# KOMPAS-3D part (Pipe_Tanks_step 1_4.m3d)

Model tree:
1. X Axis
2. Y Axis
3. Z Axis  (labels: Pipe Dn 50; Bend 90 Dn 50; C:\Program Files\ASCON\KOMPAS-3D V10\Sys\graphic.lyt; Pipe_Tanks_step 1_4.m3d)
     Òîëùèíà ñòåíêè 1 = 1

Referenced files in C:\Documents and Settings\kashirsky\Мои документы\Camtasia Studio\Pipelines3D\Tanks\: Tanks_step 1.a3d, Tanks_step 1.spw
Referenced files in C:\Documents and Settings\kashirsky\Мои документы\Camtasia Studio\Pipelines3D\Tanks\Tanks_step 1_Pipes\: Pipe_Tanks_step 1_4.m3d
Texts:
  Pipe Dn 50
  Steel ASTM A295
  Three Point Plane
  Plane at Angle
  Line and Point Plane
  Axis through Two Vertices
  Axis of Feature
  Axis of Conical Surface
  Axis through Edge
  Trim by Surface
  Trim by Sketch
  Feature with No History
  Intersection Axis of Two Planes
  Two Line Plane
  Line and Face Plane
  Bend by line
  Hole in sheet body
  Cut in sheet body
  Point in CM
  Linear Dimension from Line to Point
  Surface Finish Symbol
  Geometric Tolerance Symbol
  Leader #1
  Leader #2
  Leader #3
  Shape Deviations and Datum
  Node point number
  Mark of coordination axis
  Node point designation
  Mark/Reference designation with leader
  Mark/reference designation on line
  Mark/Reference designation without leader
  Bend 90 Dn 50
  Plane of section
